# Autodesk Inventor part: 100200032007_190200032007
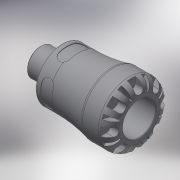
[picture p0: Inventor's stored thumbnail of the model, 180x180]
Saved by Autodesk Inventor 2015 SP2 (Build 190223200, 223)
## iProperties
Created: 2016-12
Part Number: 100200032007_190200032007
Material: Generic
Description: PLASSON MALE ADAPTOR 32X3/4" SERIES 1
Document SubType Name: Modeling
Designer: KIM
Mass: 447.839 g
Surface Area: 722.341 cm^2
Volume: 447.839 cm^3
Density: 1 g/cm^3
Appearance: Default
Author: KIM
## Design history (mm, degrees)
derived "1002.ipt"
feature "Solid1::1002.ipt"
tag "TaggingFeature1"
body "Solid1"
other parameters: "d0" = 82, "d1" = 23.1, "d2" = 32, "d4" = 58, "d6" = 55, "d8" = 49.3, "d13" = 7.2, "d14" = 7.2, "d15" = 0, "d17" = 360 deg, "d19" = 8 deg, "d20" = 0.64, "d21" = 0.64, "d22" = 8 deg, "d24" = 0, "d26" = 360 deg, "d32" = 0.925, "d33" = 5.8, "d34" = 26.441, "d35" = 6.4, "d38" = 17, "d39" = 0.79323, "d42" = 11.2, "d43" = 7.36, "d45" = 14.112, "d46" = 0, "d59" = 360 deg, "d61" = 9.52, "d62" = 0.64, "d64" = 0, "d65" = 0.58, "d_" = 32, "E_" = 58, "H_" = 82, "l_" = 55, "R_" = 26.441, "l_2" = 17, "d9" = 9, "d11" = 58
